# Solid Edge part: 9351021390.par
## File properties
Title: 9351021390
Subject: Piedino diametro 45 - M10
Author: a_mazzi
Comments: PU33
Template: Zama.par
Last saved by: v_lucarelli
Revision: 28
Application: Solid Edge
Tipo di contenuto documento: 0
Material: Zama
Company: EFFEBI S.p.A.
custom2: 2001-08-01
DIMENSIONI: .
Densità: 6000.000 kg/m^3
Precisione: 0.99
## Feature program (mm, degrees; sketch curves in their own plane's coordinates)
sketch for "unnamed RevolvedProtrusion 1" plane through (0, 0, 0) normal (0, -1, 0) x-axis (1, 0, 0)
  line (-10, 8) -> (-21.9178, 2.5194)
  arc centre (-21.5, 1.6109) radius 1 from (-21.9178, 2.5194) to (-22.2947, 1.0038) ccw
  line (-20, -2) -> (-22.2947, 1.0038)
  line (-18.5, -2) -> (-20, -2)
  line (-18.5, -2) -> (-18.5, -0.5)
  line (-18.5, -0.5) -> (-17, -0.5)
  line (-17, -0.5) -> (-17, 3)
  line (-9, 6.6789) -> (-17, 3)
  line (-7, 6.6789) -> (-9, 6.6789)
  line (-7, 0) -> (-7, 6.6789)
  line (-7, 0) -> (0, 0)
  line (0, 0) -> (0, 8)
  line (0, 8) -> (-10, 8)
revolve "unnamed RevolvedProtrusion 1" add full turn 360 deg about sketch line (0, 0) -> (0, 8)
sketch for "unnamed Protrusion 1" plane through (0, 0, 8) normal (0, 0, 1) x-axis (1, 0, 0)
  circle centre (0, 0) radius 6.5
extrude "unnamed Protrusion 1" add finite 4 along +normal
sketch for "unnamed Protrusion 2" plane through (0, 0, 0) normal (0, 0, -1) x-axis (0, 1, 0)
extrude "unnamed Protrusion 2" add through along -normal
sketch for "unnamed Protrusion 3" plane through (2, 0, 0) normal (0, 0, -1) x-axis (0, 1, 0)
extrude "unnamed Protrusion 3" add through along -normal
pattern "unnamed Pattern 1" of "unnamed Protrusion 3", "unnamed Protrusion 2"
extrude "unnamed Protrusion 4" add through
extrude "unnamed Protrusion 5" add through
extrude "unnamed Protrusion 6" add through
extrude "unnamed Protrusion 7" add through
extrude "unnamed Protrusion 8" add through
extrude "unnamed Protrusion 9" add through
sketch for "Foro_1" plane through (0, 0, 12) normal (0, 0, 1) x-axis (0, 1, 0)
  hole centre (0, 0) bore radius 4.188
hole "Foro_1" nominal diameter 10 through  ThreadDepth = 2 mm
sketch for "ExtrudedProtrusion_2" plane through (0, 0, 2) normal (0, 0, -1) x-axis (0, 1, 0)
  circle centre (0, 0) radius 5
extrude "ExtrudedProtrusion_2" add finite 30 along -normal  Profile_Plane1_Distance = 2 mm
thread "unnamed Thread 1"
fillet "Rotondo_1" radius 0.5
sketch for "FELTRO" plane through (0, 0, 0) normal (0, 0, -1) x-axis (0, 1, 0)
  circle centre (0, 0) radius 15.5
extrude "FELTRO" add finite 3 along +normal
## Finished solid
Body 1: solid body, 54 faces, 115 edges, 64 vertices, 1 internal void.
  Faces by surface: plane 28, cylinder 18, cone 6, torus 2
  Edges by curve: circle 59, line 40, intersection 16
Bounding box of the edges (mm; curved faces can reach further): 44.589 x 44.589 x 35.000, from (-22.2947, -22.2947, -3) to (22.2947, 22.2947, 32).
Cylindrical faces by radius (mm): R2.5 x8, R4.188 x1, R5 x1, R6.5 x1, R7 x4, R15.5 x1, R17 x1, R18.5 x1
Conical faces (half-angle, radius in mm at the cone's reference point): 37.3767 deg R22.2947 x1, 65.3039 deg R10 x1, 65.3039 deg R17 x4
Toroidal faces (ring radius, tube radius in mm): R6 r0.5 x1, R21.5 r1 x1
Planar faces by outward normal: +x 2, +y 2, +z 8, -x 2, -y 2, -z 12
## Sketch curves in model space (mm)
line (-10, 0, 8) -> (-21.9178, 0, 2.5194)
arc centre (-21.5, 0, 1.6109) radius 1 from (-21.9178, 0, 2.5194) through (-22.4704, 0, 1.8522) to (-22.2947, 0, 1.0038)
line (-20, 0, -2) -> (-22.2947, 0, 1.0038)
line (-18.5, 0, -2) -> (-20, 0, -2)
line (-18.5, 0, -2) -> (-18.5, 0, -0.5)
line (-18.5, 0, -0.5) -> (-17, 0, -0.5)
line (-17, 0, -0.5) -> (-17, 0, 3)
line (-9, 0, 6.6789) -> (-17, 0, 3)
line (-7, 0, 6.6789) -> (-9, 0, 6.6789)
line (-7, 0, 0) -> (-7, 0, 6.6789)
line (-7, 0, 0) -> (0, 0, 0)
line (0, 0, 0) -> (0, 0, 8)
line (0, 0, 8) -> (-10, 0, 8)
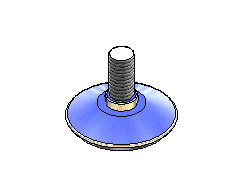
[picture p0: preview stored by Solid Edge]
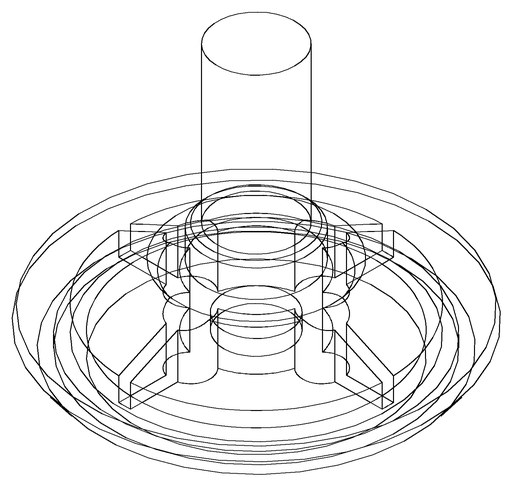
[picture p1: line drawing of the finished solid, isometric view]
